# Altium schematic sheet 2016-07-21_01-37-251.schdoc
size 265 x 165 mm; SheetNumber: 1; SheetTotal: 1
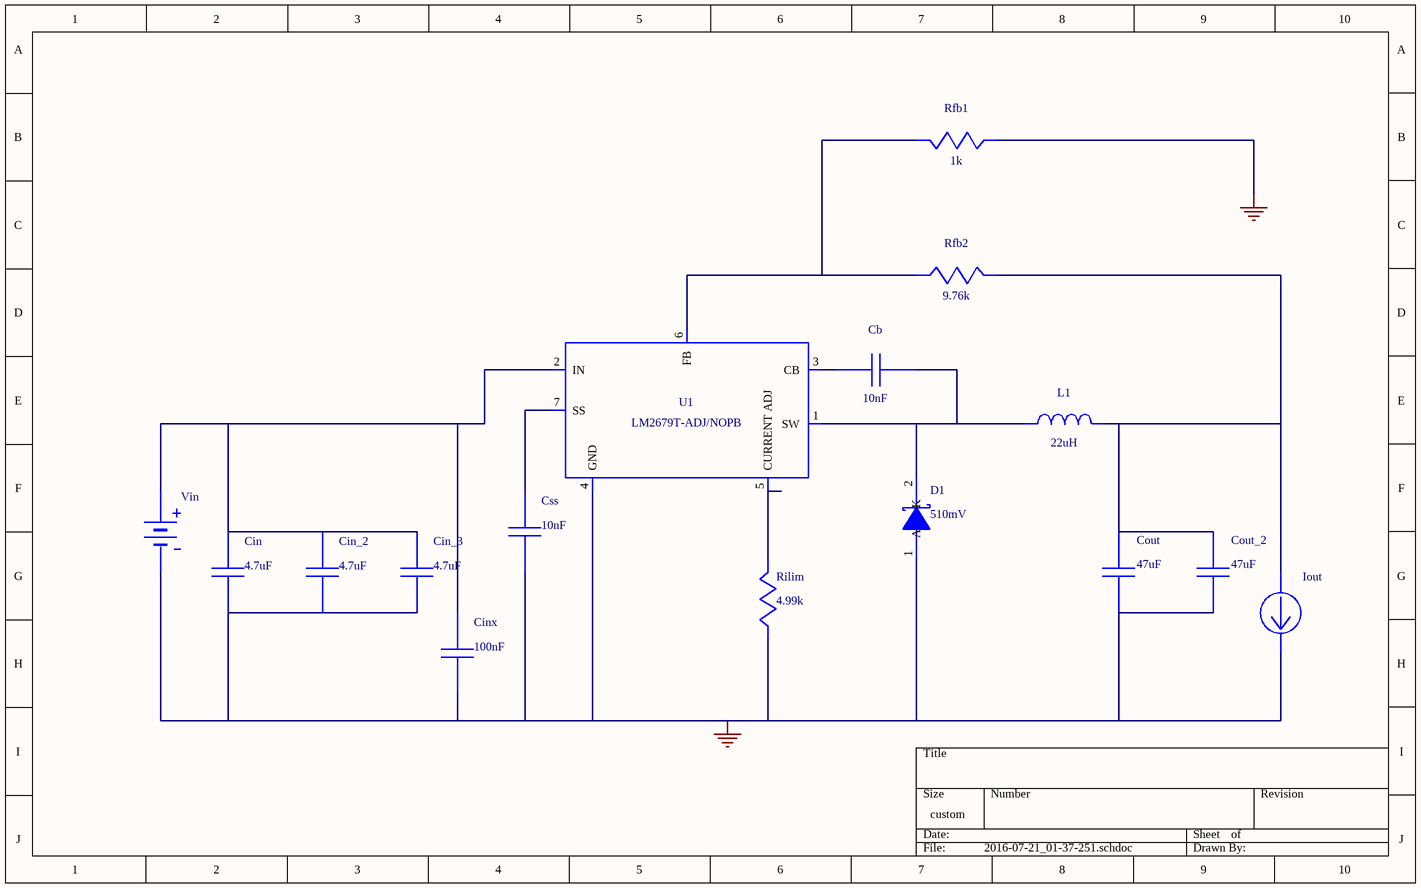
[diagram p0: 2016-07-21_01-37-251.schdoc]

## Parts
Cb  value 10nF  (hidden comment: GRM216R71H103KA01D)
Cin  value 4.7uF  (hidden comment: GRM31CR71H475KA12L)
Cin_2  value 4.7uF  (hidden comment: GRM31CR71H475KA12L)
Cin_3  value 4.7uF  (hidden comment: GRM31CR71H475KA12L)
Cinx  value 100nF  (hidden comment: C0805C104K5RACTU)
Cout  value 47uF  (hidden comment: C3216X5R1E476M160AC)
Cout_2  value 47uF  (hidden comment: C3216X5R1E476M160AC)
Css  value 10nF  (hidden comment: GRM216R71H103KA01D)
D1  value 510mV  (hidden comment: 50WQ04FNPBF)
Iout  WB_CURRENT_LOAD  (value not drawn)
L1  value 22uH  (hidden comment: SER2915H-223KL)
Rfb1  value 1k  (hidden comment: ERJ-6ENF1001V)
Rfb2  value 9.76k  (hidden comment: ERJ-6ENF9761V)
Rilim  value 4.99k  (hidden comment: ERJ-6ENF4991V)
U1  LM2679T-ADJ/NOPB
Vin  WB_BATTERY  (value not drawn)

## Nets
0: Cin.2 Cin_2.2 Cin_3.2 Cinx.2 Cout.2 Cout_2.2 Css.2 D1.1(A) D1.3(A) Iout.2(-) Rfb1.2 Rilim.2 U1.4(GND) Vin.2(-)
NetCb_1: Cb.1 D1.2(K) L1.1 U1.1(SW)
NetCb_2: Cb.2 U1.3(CB)
NetCin_1: Cin.1 Cin_2.1 Cin_3.1 Cinx.1 U1.2(IN) Vin.1(+)
NetCout_1: Cout.1 Cout_2.1 Iout.1(+) L1.2 Rfb2.1
NetCss_1: Css.1 U1.7(SS)
NetRfb1_1: Rfb1.1 Rfb2.2 U1.6(FB)
NetRilim_1: Rilim.1 U1.5(CURRENT_ADJ)

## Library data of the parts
Cb Css = GRM216R71H103KA01D: GRM216R71H103KA0; Manufacturer Name: MuRata
Cin Cin_2 Cin_3 = GRM31CR71H475KA12L: GRM31CR71H475KA1; Manufacturer Name: MuRata
Cinx = C0805C104K5RACTU: Manufacturer Name: Kemet
Cout Cout_2 = C3216X5R1E476M160AC: C3216X5R1E476M16; Manufacturer Name: TDK
D1 = 50WQ04FNPBF: Manufacturer Name: Vishay-Semiconductor
L1 = SER2915H-223KL: Manufacturer Name: Coilcraft
Rfb1 = ERJ-6ENF1001V: Manufacturer Name: Panasonic
Rfb2 = ERJ-6ENF9761V: Manufacturer Name: Panasonic
Rilim = ERJ-6ENF4991V: Manufacturer Name: Panasonic
U1 = LM2679T-ADJ/NOPB: Manufacturer Name: Texas Instruments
